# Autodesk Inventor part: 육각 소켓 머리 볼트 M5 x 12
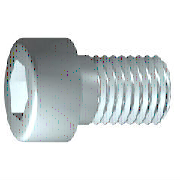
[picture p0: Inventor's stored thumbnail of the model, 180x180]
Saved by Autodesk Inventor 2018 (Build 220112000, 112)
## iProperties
IsCustomPart: 1
Created: 2012-02
Part Number: 육각 소켓 머리 볼트 M5 x 12
Material: 스테인리스강
Description: 6각 소켓 머리 캡 나사
Document SubType Name: Modeling
Standard: ISO 4762
Designer: mdu-01
Standard Revision: Fourth edition 2004-03-01
Standards Organization: ISO
Language: ko-KR
Size Designation: M5 x 12
Categories: <MemberInstance><Categories><Category DisplayName="조임쇠" InternalName="e4da775c-781d-43d5-af7c-5136215cf5a6" Mnemonic="FSTN"><Category DisplayName="볼트" InternalN
Density: 7.75 g/cm^3
Appearance: 반광택
Author: mdu-01
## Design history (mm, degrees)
sketch "스케치1"
  geometry: L1 (-1.167, 0)-(12, 0); L2 (12, 0)-(12, 2.5); L3 (12, 2.5)-(2, 2.5); L4 (2, 2.5)-(1.509, 2.5); L5 (1.509, 2.5)-(0, 2.5); L6 (0, 2.5)-(0, 4.25); L7 (0, 4.25)-(-5, 4.25); L8 (-5, 4.25)-(-5, 2.309); L9 (-5, 2.309)-(-2.5, 2.309); L10 (-2.5, 2.309)-(-1.167, 0); L11 (-8.4, 0)-(15.4, 0) reference; L12 (0, -0.85)-(0, 5.1) reference; L13 (2, 2.5)-(0, 2.5)
  constraints: 22 end point, 6 parallel, 2 collinear, 2 perpendicular, 1 horizontal, 1 point on line
  dimensions: "d1" = 10 distance from line of L3.end L2 (= GEL); "d2" = 0.49086 distance of L4.end L3.end (computed from GAL); "d3" = 5 distance between parallel lines of L8 L6 (= KOH); "d4" = 2.5 distance of L8.end L9.end (= INTI); "d5" = 60 deg angle of L10 L1; "d6" = 5 diameter of L3 L1 (= GD); "d7" = 5 diameter of L5 L1 (= BDM); "d8" = 4.6188 diameter of L9 L1 (= 1.1547 x SW); "d9" = 8.5 diameter of L7 L1 (= KOD); "d26" = 12 distance between parallel lines of L12 L2 (= NLG)
revolve "본체" sketch "스케치1" stored, may be unused: angle "d10" = 90 deg
sketch "스케치2"
  geometry: L1 (0, -5.95)-(0, 5.95) reference; L2 (-5.95, 0)-(5.95, 0) reference; L3 (2.309, 0)-(1.155, -2); L4 (1.155, -2)-(-1.155, -2); L5 (-1.155, -2)-(-2.309, 0); L6 (-2.309, 0)-(-1.155, 2); L7 (-1.155, 2)-(1.155, 2); L8 (1.155, 2)-(2.309, 0); 2 further points
  constraints: 12 end point, 1 coincident, 1 horizontal alignment, 1 point on line, 12 other
extrude "슬롯" join sketch "스케치2" stored distance "d11" = 10; taper "d12" = 0 deg
workplane "Work Plane1"
fillet "Fillet2" dims "d30" = 0.05 (= R)
body "Solid1"
fillet "모깎기1" dims "d17" = 0.5 (= RR)
feature "스레드" dims "d13" = 10 (= GEL), "d14" = 0
chamfer "모따기1" distance "d15" = 0.49076 (= -0.5 x SPD + 0.5 x GD); stored, may be unused: second distance "d16" = 0.49076 (= GUL), angle "d27" = 45 deg
other parameters: "GD" = 5 [user parameter; used in 2 equation terms], "NLG" = 12 [user parameter; used in 1 equation term], "GEL" = 10 [user parameter; used in 2 equation terms], "KOD" = 8.5 [user parameter; used in 1 equation term], "KOH" = 5 [user parameter; used in 1 equation term], "INTI" = 2.5 [user parameter; used in 1 equation term], "GAL" = 0.49076 (= 0.61345 x PTC) [user parameter; used in 1 equation term], "GUL" = 0.49076 (= 0.61345 x PTC) [user parameter; used in 1 equation term], "BDM" = 5 (= NND) [user parameter; used in 1 equation term], "SW" = 4 [user parameter; used in 2 equation terms], "RR" = 0.5 [user parameter; used in 1 equation term], "SPD" = 4.01848 (= NND - 1.2269 x PTC) [user parameter; used in 1 equation term], "d19" = 0, "d28" = 0, "d29" = 0, "R" = 0.05 [user parameter; used in 1 equation term], "TOA" = 30 deg [user parameter], "GD1" = 4.01848 (= THREADDIA - 1.2269 x PTC) [user parameter], "THREADDIA" = 5 [user parameter; used in 1 equation term], "FAWI" = 45 deg [user parameter], "TPU" = 12.5 (computed from PTC) [user parameter], "PTC" = 0.8 [user parameter; used in 5 equation terms], "NND" = 5 [user parameter; used in 2 equation terms], "E0" = 4.62 (= 1.155 x SW) [user parameter]
